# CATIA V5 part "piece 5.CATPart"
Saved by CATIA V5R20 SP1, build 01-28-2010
Part number: piece 5
Bounding box of the stored display mesh (mm): x -20 to 120, y -20 to 120, z 0 to 10
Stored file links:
  D:\Dropbox\IAO_2011\MMS_GR1\jdubreuilr\jdubreuilr\jdubreuilr\piece 5.CATPart
  C:\Users\Jean-Philippe\Desktop\projet IAO\assemblage\piece 5 j.CATPart
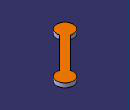
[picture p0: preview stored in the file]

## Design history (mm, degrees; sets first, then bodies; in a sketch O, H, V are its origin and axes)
Set1
  Point1: type OnPlane, Support xy-plane, H 0, V 0, Direction (1, 0, 0)
  Point2: type OnPlane, Support xy-plane, H 100, V 100, Direction (1, 0, 0)
  Line1: type Normal, RefPoint Point2, RefSkin end face of Pad1, Start 0, End 20
  Line2: type Normal, RefPoint Point1, RefSkin end face of Pad1, Start 0, End 20
Body1 (main body)
  Sketch1 on xy-plane, origin (0, 0, 0), H (1, 0, 0), V (0, 1, 0)
    arc A1 centre (0, 0) radius 20 from (5.1764, 19.3185) to (19.3185, 5.1764) ccw
    arc A2 centre (100, 100) radius 20 from (94.8236, 80.6815) to (80.6815, 94.8236) ccw
    point P3 (100, 100)
    point P5 (94.8236, 80.6815)
    reference projected point E1 (100, 100)
    line L1 (80.6815, 94.8236) -> (5.1764, 19.3185)
    line L2 (94.8236, 80.6815) -> (19.3185, 5.1764)
    point P6 (94.8236, 80.6815)
    axis line L3 (100, 100) -> (0, 0)
    radius A1 = 20
    radius A2 = 20
    distance L1 L3 = 10
    distance L2 L3 = 10
    coincidence: P3 E1, P6 A2, P5 P6
  Pad1: profile Sketch1, direction (0, 0, 1), length 10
